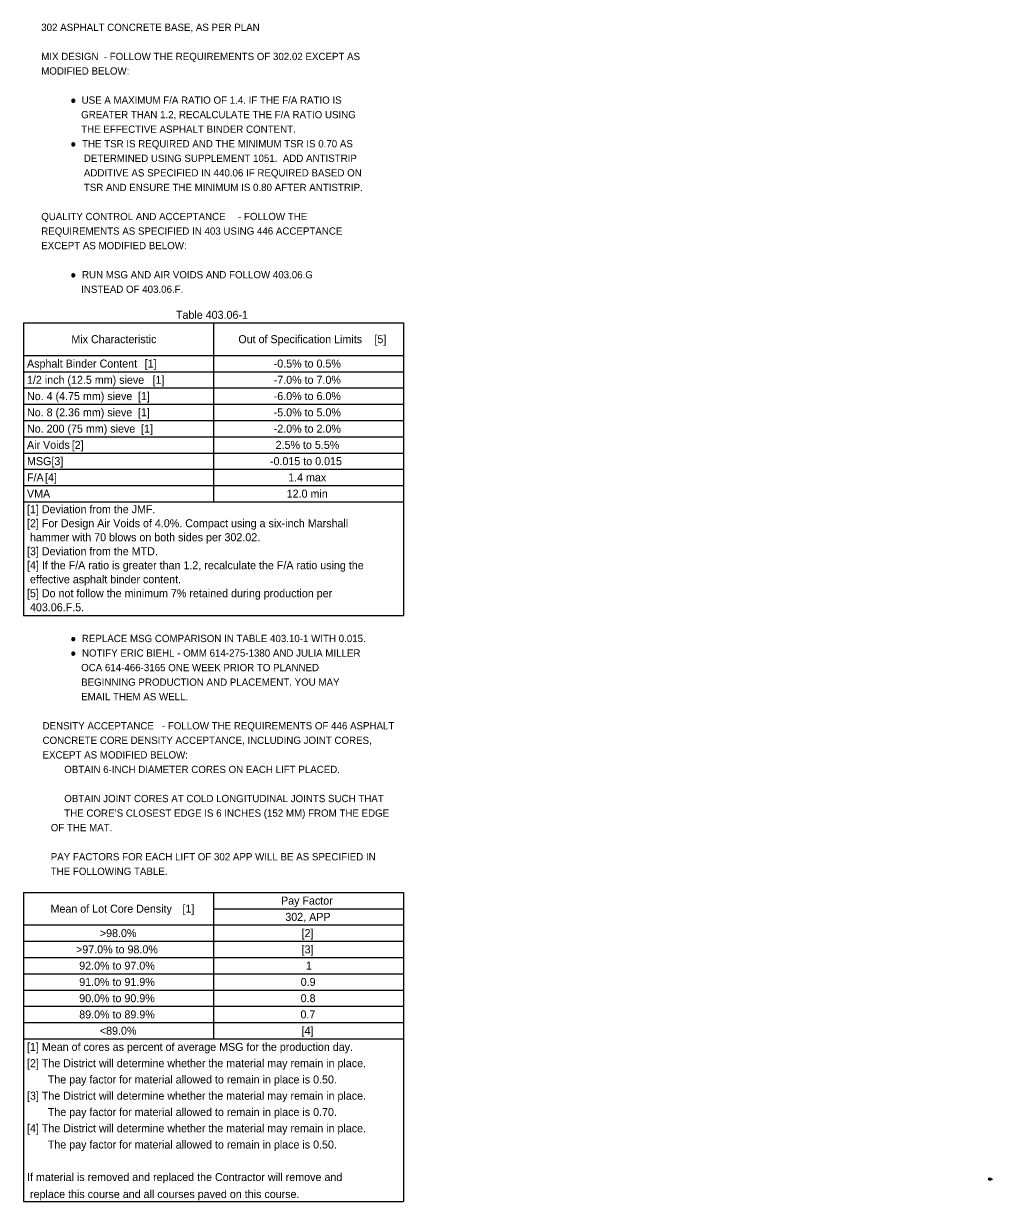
# Model space of a CAD drawing. Extents: x 0 to 55.4, y -1.6 to 22.
# Drawn here: x 36.79 to 55.44, y -1.58 to 21.08 of the extents above; entities that cross this region are included whole.
import ezdxf

# ---------------------------------------------------------------- set-up
doc = ezdxf.new("R2010")
doc.units = 0
doc.layers.add('Default', color=7, linetype='Continuous')
doc.layers.add('SH_Text', color=7, linetype='Continuous')

msp = doc.modelspace()

# ---------------------------------------------------------------- linework, layer by layer
at = {"layer": 'Default'}
for p, q in [((36.793, 15.322), (44.106, 15.322)), ((36.793, 15.322), (36.793, 9.689)), ((40.449, 15.322), (40.449, 11.88)), ((44.106, 15.322), (44.106, 9.689)), ((36.793, 14.696), (44.106, 14.696)), ((36.793, 14.383), (44.106, 14.383)), ((36.793, 14.07), (44.106, 14.07)), ((36.793, 13.757), (44.106, 13.757)), ((36.793, 13.444), (44.106, 13.444)), ((36.793, 13.131), (44.106, 13.131)), ((36.793, 12.818), (44.106, 12.818)), ((36.793, 12.506), (44.106, 12.506)), ((36.793, 12.193), (44.106, 12.193)), ((36.793, 11.88), (44.106, 11.88)), ((36.793, 9.689), (44.106, 9.689)), ((36.793, 4.362), (44.106, 4.362)), ((36.793, 4.362), (36.793, -1.583)), ((40.449, 4.362), (40.449, 1.546)), ((44.106, 4.362), (44.106, -1.583)), ((40.449, 4.05), (44.106, 4.05)), ((36.793, 3.737), (44.106, 3.737)), ((36.793, 3.424), (44.106, 3.424)), ((36.793, 3.111), (44.106, 3.111)), ((36.793, 2.798), (44.106, 2.798)), ((36.793, 2.485), (44.106, 2.485)), ((36.793, 2.172), (44.106, 2.172)), ((36.793, 1.859), (44.106, 1.859)), ((36.793, 1.546), (44.106, 1.546)), ((55.36, -1.152), (55.412, -1.152)), ((55.386, -1.152), (55.436, -1.152)), ((36.793, -1.583), (44.106, -1.583))]:
    msp.add_line(p, q, dxfattribs=at)
msp.add_circle((55.386, -1.152), 0.026, dxfattribs=at)

# ---------------------------------------------------------------- texts
for s, height, p in [('Table 403.06-1', 0.154, (39.725, 15.401)), ('Mix Characteristic', 0.154, (37.713, 14.932)), ('Out of Specification Limits', 0.154, (40.926, 14.932)), ('[5]', 0.154, (43.544, 14.932)), ('Asphalt Binder Content', 0.154, (36.859, 14.463)), ('[1]', 0.154, (39.123, 14.463)), ('-0.5% to 0.5%', 0.154, (41.606, 14.463)), ('1/2 inch (12.5 mm) sieve', 0.154, (36.859, 14.15)), ('[1]', 0.154, (39.274, 14.15)), ('-7.0% to 7.0%', 0.154, (41.606, 14.15)), ('No. 4 (4.75 mm) sieve', 0.154, (36.859, 13.837)), ('[1]', 0.154, (38.993, 13.837)), ('-6.0% to 6.0%', 0.154, (41.606, 13.837)), ('No. 8 (2.36 mm) sieve', 0.154, (36.859, 13.524)), ('[1]', 0.154, (38.993, 13.524)), ('-5.0% to 5.0%', 0.154, (41.606, 13.524)), ('No. 200 (75 mm) sieve', 0.154, (36.859, 13.211)), ('[1]', 0.154, (39.054, 13.211)), ('-2.0% to 2.0%', 0.154, (41.606, 13.211)), ('Air Voids', 0.154, (36.859, 12.898)), ('[2]', 0.154, (37.72, 12.898)), ('2.5% to 5.5%', 0.154, (41.643, 12.898)), ('MSG', 0.154, (36.859, 12.585)), ('[3]', 0.154, (37.329, 12.585)), ('-0.015 to 0.015', 0.154, (41.534, 12.585)), ('F/A', 0.154, (36.859, 12.272)), ('[4]', 0.154, (37.205, 12.272)), ('1.4 max', 0.154, (41.884, 12.272)), ('VMA', 0.154, (36.859, 11.959)), ('12.0 min', 0.154, (41.856, 11.959)), ('[1] Deviation from the JMF.', 0.154, (36.859, 11.66)), ('[2] For Design Air Voids of 4.0%. Compact using a six-inch Marshall', 0.154, (36.859, 11.39)), (' hammer with 70 blows on both sides per 302.02.', 0.154, (36.859, 11.121)), ('[3] Deviation from the MTD.', 0.154, (36.859, 10.851)), ('[4] If the F/A ratio is greater than 1.2, recalculate the F/A ratio using the', 0.154, (36.859, 10.582)), (' effective asphalt binder content.', 0.154, (36.859, 10.312)), ('[5] Do not follow the minimum 7% retained during production per', 0.154, (36.859, 10.043)), (' 403.06.F.5.', 0.154, (36.859, 9.773)), ('Mean of Lot Core Density', 0.154, (37.312, 3.973)), ('[1]', 0.154, (39.85, 3.973)), ('Pay Factor', 0.154, (41.747, 4.129)), ('302, APP', 0.154, (41.83, 3.816)), ('>98.0%', 0.154, (38.261, 3.503)), ('[2]', 0.154, (42.143, 3.503)), ('>97.0% to 98.0%', 0.154, (37.803, 3.19)), ('[3]', 0.154, (42.143, 3.19)), ('92.0% to 97.0%', 0.154, (37.864, 2.877)), ('1', 0.154, (42.227, 2.877)), ('91.0% to 91.9%', 0.154, (37.864, 2.564)), ('0.9', 0.154, (42.126, 2.564)), ('90.0% to 90.9%', 0.154, (37.864, 2.251)), ('0.8', 0.154, (42.125, 2.251)), ('89.0% to 89.9%', 0.154, (37.864, 1.938)), ('0.7', 0.154, (42.121, 1.938)), ('<89.0%', 0.154, (38.261, 1.625)), ('[4]', 0.154, (42.143, 1.625)), ('[1] Mean of cores as percent of average MSG for the production day.', 0.154, (36.859, 1.313)), ('[2] The District will determine whether the material may remain in place.', 0.154, (36.859, 1)), ('       The pay factor for material allowed to remain in place is 0.50.', 0.154, (36.859, 0.687)), ('[3] The District will determine whether the material may remain in place.', 0.154, (36.859, 0.374)), ('       The pay factor for material allowed to remain in place is 0.70.', 0.154, (36.859, 0.061)), ('[4] The District will determine whether the material may remain in place.', 0.154, (36.859, -0.252)), ('       The pay factor for material allowed to remain in place is 0.50.', 0.154, (36.859, -0.565)), ('If material is removed and replaced the Contractor will remove and', 0.154, (36.859, -1.191)), (' replace this course and all courses paved on this course.', 0.154, (36.859, -1.518)), ('P.7', 0.00328, (55.383, -1.162)), ('1', 0.00328, (55.385, -1.146)), ('Drawing', 0.00328, (55.419, -1.146)), ('1:1', 0.00328, (55.419, -1.162))]:
    msp.add_text(s, height=height, dxfattribs=at).set_placement(p)
at = {"layer": 'SH_Text'}
for s, p in [('302 ASPHALT CONCRETE BASE, AS PER PLAN', (37.133, 20.94)), ('MIX DESIGN', (37.133, 20.38)), (' - FOLLOW THE REQUIREMENTS OF 302.02 EXCEPT AS', (38.285, 20.38)), ('MODIFIED BELOW:', (37.133, 20.1)), ('●  USE A MAXIMUM F/A RATIO OF 1.4. IF THE F/A RATIO IS', (37.693, 19.54)), ('    GREATER THAN 1.2, RECALCULATE THE F/A RATIO USING', (37.693, 19.26)), ('    THE EFFECTIVE ASPHALT BINDER CONTENT.', (37.693, 18.98)), (' THE TSR IS REQUIRED AND THE MINIMUM TSR IS 0.70 AS', (37.866, 18.7)), ('● ', (37.693, 18.7)), ('     DETERMINED USING SUPPLEMENT 1051.  ADD ANTISTRIP', (37.693, 18.42)), ('     ADDITIVE AS SPECIFIED IN 440.06 IF REQUIRED BASED ON', (37.693, 18.14)), ('     TSR AND ENSURE THE MINIMUM IS 0.80 AFTER ANTISTRIP.', (37.693, 17.86)), ('QUALITY CONTROL AND ACCEPTANCE', (37.133, 17.3)), (' - FOLLOW THE', (40.868, 17.3)), ('REQUIREMENTS AS SPECIFIED IN 403 USING 446 ACCEPTANCE', (37.133, 17.02)), ('EXCEPT AS MODIFIED BELOW:', (37.133, 16.74)), (' RUN MSG AND AIR VOIDS AND FOLLOW 403.06.G', (37.866, 16.18)), ('● ', (37.693, 16.18)), ('    INSTEAD OF 403.06.F.', (37.693, 15.9)), ('  REPLACE MSG COMPARISON IN TABLE 403.10-1 WITH 0.015.', (37.811, 9.18)), ('●', (37.693, 9.18)), ('● ', (37.693, 8.9)), (' NOTIFY ERIC BIEHL - OMM 614-275-1380 AND JULIA MILLER', (37.866, 8.9)), ('    OCA 614-466-3165 ONE WEEK PRIOR TO PLANNED', (37.693, 8.62)), ('    BEGINNING PRODUCTION AND PLACEMENT. YOU MAY', (37.693, 8.34)), ('    EMAIL THEM AS WELL.', (37.693, 8.06)), ('    DENSITY ACCEPTANCE', (36.95, 7.5)), (' - FOLLOW THE REQUIREMENTS OF 446 ASPHALT', (39.403, 7.5)), ('    CONCRETE CORE DENSITY ACCEPTANCE, INCLUDING JOINT CORES,', (36.95, 7.22)), ('    EXCEPT AS MODIFIED BELOW:', (36.95, 6.94)), ('     OBTAIN 6-INCH DIAMETER CORES ON EACH LIFT PLACED.', (37.316, 6.66)), ('     OBTAIN JOINT CORES AT COLD LONGITUDINAL JOINTS SUCH THAT', (37.316, 6.1)), ('     THE CORE’S CLOSEST EDGE IS 6 INCHES (152 MM) FROM THE EDGE', (37.316, 5.82)), ('OF THE MAT.', (37.316, 5.54)), ('PAY FACTORS FOR EACH LIFT OF 302 APP WILL BE AS SPECIFIED IN', (37.316, 4.98)), ('THE FOLLOWING TABLE.', (37.316, 4.7))]:
    msp.add_text(s, height=0.14, dxfattribs=at).set_placement(p)

doc.saveas('drawing.dxf')
